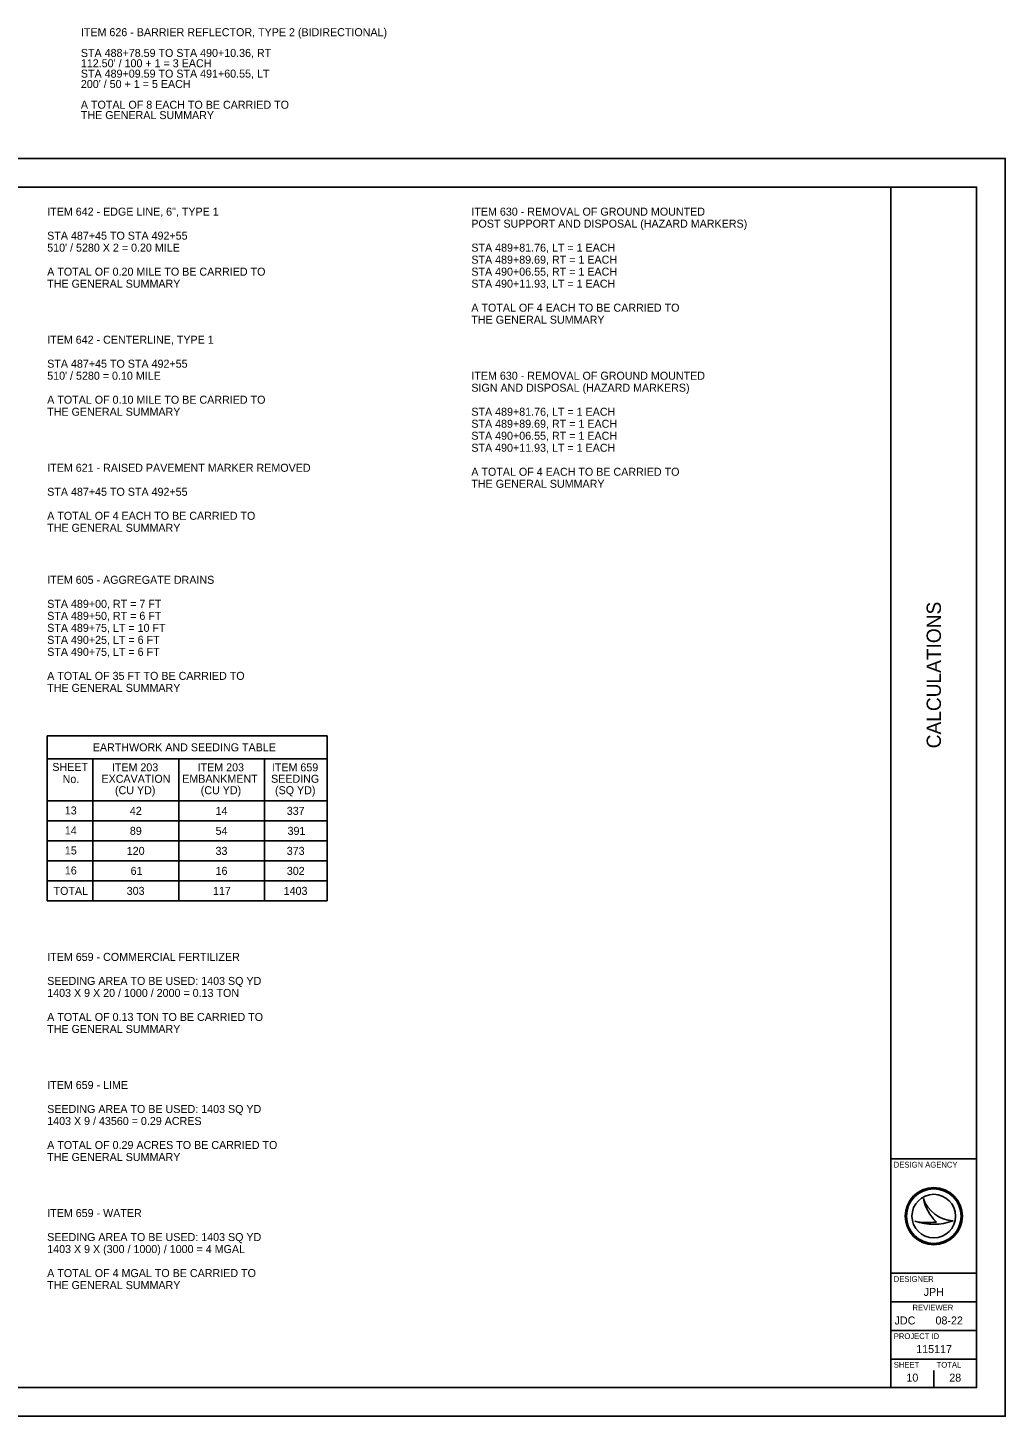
# Model space of a CAD drawing. Extents: x 0 to 34, y 0 to 24.3.
# Drawn here: x 16.9 to 34, y 0 to 24.29 of the extents above; entities that cross this region are included whole.
import ezdxf

# ---------------------------------------------------------------- set-up
doc = ezdxf.new("R2010")
doc.units = 0
for name, color, linetype in [('SH_Border', 7, 'Continuous'), ('SH_Cut_Line', 7, 'Continuous'), ('SH_Data', 7, 'Continuous'), ('TX_P_1', 7, 'Continuous')]:
    doc.layers.add(name, color=color, linetype=linetype)

msp = doc.modelspace()

# ---------------------------------------------------------------- linework, layer by layer
at = {"layer": 'SH_Border'}
for p, q in [((32, 0.5), (32, 21.5)), ((32, 4.5), (33.5, 4.5)), ((32, 2.5), (33.5, 2.5)), ((32, 2), (33.5, 2)), ((32, 1.5), (33.5, 1.5)), ((32, 1), (33.5, 1))]:
    msp.add_line(p, q, dxfattribs=at)
msp.add_lwpolyline([(1.5, 21.5), (33.5, 21.5), (33.5, 0.5), (1.5, 0.5)], close=True, dxfattribs=at)
at = {"layer": 'SH_Cut_Line'}
msp.add_lwpolyline([(0, 0), (34, 0), (34, 22), (0, 22)], close=True, dxfattribs=at)
at = {"layer": 'SH_Data'}
for p, q in [((32.567, 3.81), (32.567, 3.81)), ((32.417, 3.41), (32.417, 3.41)), ((32.75, 3.5), (32.75, 3.5)), ((33.087, 3.419), (33.087, 3.419)), ((32.75, 0.5), (32.75, 0.8)), ((32.375, 0.675), (32.375, 0.675))]:
    msp.add_line(p, q, dxfattribs=at)
for radius in [0.5, 0.477, 0.477, 0.382]:
    msp.add_circle((32.75, 3.5), radius, dxfattribs=at)
for centre, radius, start, end in [((33.116, 3.998), 0.58, 198.9257, 198.9319), ((33.347, 3.97), 0.796, 191.6379, 191.6421), ((33.116, 3.998), 0.58, 198.9319, 267.1657), ((33.347, 3.97), 0.796, 191.6421, 226.0947), ((32.739, 4.37), 1.013, 251.4576, 290.0832), ((32.648, 4.654), 1.266, 259.4964, 259.4995), ((32.739, 4.37), 1.013, 251.4527, 251.4576), ((32.648, 4.654), 1.266, 259.4995, 276.6672)]:
    msp.add_arc(centre, radius, start, end, dxfattribs=at)
at = {"layer": 'TX_P_1'}
for p, q in [((22.14, 11.9), (17.24, 11.9)), ((17.24, 11.9), (17.24, 9.014)), ((22.14, 11.9), (22.14, 9.014)), ((22.14, 11.5), (17.24, 11.5)), ((18.04, 11.5), (18.04, 9.014)), ((19.54, 11.5), (19.54, 9.014)), ((21.04, 11.5), (21.04, 9.014)), ((22.14, 10.764), (17.24, 10.764)), ((22.14, 10.414), (17.24, 10.414)), ((22.14, 10.064), (17.24, 10.064)), ((22.14, 9.714), (17.24, 9.714)), ((22.14, 9.364), (17.24, 9.364)), ((22.14, 9.364), (17.24, 9.364)), ((22.14, 9.014), (17.24, 9.014))]:
    msp.add_line(p, q, dxfattribs=at)

# ---------------------------------------------------------------- texts
at = {"layer": 'SH_Data'}
msp.add_text('CALCULATIONS', height=0.25, rotation=90, dxfattribs=at).set_placement((32.875, 11.683))
for s, height, p in [('DESIGN AGENCY', 0.1, (32.05, 4.35)), ('DESIGNER', 0.1, (32.05, 2.35)), ('JPH', 0.14, (32.573, 2.105)), ('REVIEWER', 0.1, (32.378, 1.85)), ('JDC', 0.14, (32.064, 1.605)), ('08-22', 0.14, (32.78, 1.605)), ('PROJECT ID', 0.1, (32.05, 1.35)), ('115117', 0.14, (32.443, 1.105)), ('SHEET', 0.1, (32.05, 0.85)), ('10', 0.14, (32.271, 0.605)), ('TOTAL', 0.1, (32.8, 0.85)), ('28', 0.14, (33.021, 0.605))]:
    msp.add_text(s, height=height, dxfattribs=at).set_placement(p)
at = {"layer": 'TX_P_1'}
for s, p in [('ITEM 626 - BARRIER REFLECTOR, TYPE 2 (BIDIRECTIONAL)', (17.829, 24.139)), ('STA 488+78.59 TO STA 490+10.36, RT', (17.829, 23.776)), ("112.50' / 100 + 1 = 3 EACH", (17.829, 23.595)), ('STA 489+09.59 TO STA 491+60.55, LT', (17.829, 23.414)), ("200' / 50 + 1 = 5 EACH", (17.829, 23.233)), ('A TOTAL OF 8 EACH TO BE CARRIED TO', (17.829, 22.87)), ('THE GENERAL SUMMARY', (17.829, 22.689)), ('ITEM 642 - EDGE LINE, 6", TYPE 1', (17.24, 21)), ('ITEM 630 - REMOVAL OF GROUND MOUNTED', (24.66, 21)), ('POST SUPPORT AND DISPOSAL (HAZARD MARKERS)', (24.66, 20.79)), ('STA 487+45 TO STA 492+55', (17.24, 20.58)), ("510' / 5280 X 2 = 0.20 MILE", (17.24, 20.37)), ('STA 489+81.76, LT = 1 EACH', (24.66, 20.37)), ('STA 489+89.69, RT = 1 EACH', (24.66, 20.16)), ('A TOTAL OF 0.20 MILE TO BE CARRIED TO', (17.24, 19.95)), ('STA 490+06.55, RT = 1 EACH', (24.66, 19.95)), ('THE GENERAL SUMMARY', (17.24, 19.74)), ('STA 490+11.93, LT = 1 EACH', (24.66, 19.74)), ('A TOTAL OF 4 EACH TO BE CARRIED TO', (24.66, 19.32)), ('THE GENERAL SUMMARY', (24.66, 19.11)), ('ITEM 642 - CENTERLINE, TYPE 1', (17.24, 18.76)), ('STA 487+45 TO STA 492+55', (17.24, 18.34)), ("510' / 5280 = 0.10 MILE", (17.24, 18.13)), ('ITEM 630 - REMOVAL OF GROUND MOUNTED', (24.66, 18.13)), ('SIGN AND DISPOSAL (HAZARD MARKERS)', (24.66, 17.92)), ('A TOTAL OF 0.10 MILE TO BE CARRIED TO', (17.24, 17.71)), ('THE GENERAL SUMMARY', (17.24, 17.5)), ('STA 489+81.76, LT = 1 EACH', (24.66, 17.5)), ('STA 489+89.69, RT = 1 EACH', (24.66, 17.29)), ('STA 490+06.55, RT = 1 EACH', (24.66, 17.08)), ('STA 490+11.93, LT = 1 EACH', (24.66, 16.87)), ('ITEM 621 - RAISED PAVEMENT MARKER REMOVED', (17.24, 16.52)), ('A TOTAL OF 4 EACH TO BE CARRIED TO', (24.66, 16.45)), ('THE GENERAL SUMMARY', (24.66, 16.24)), ('STA 487+45 TO STA 492+55', (17.24, 16.1)), ('A TOTAL OF 4 EACH TO BE CARRIED TO', (17.24, 15.68)), ('THE GENERAL SUMMARY', (17.24, 15.47)), ('ITEM 605 - AGGREGATE DRAINS', (17.24, 14.56)), ('STA 489+00, RT = 7 FT', (17.24, 14.14)), ('STA 489+50, RT = 6 FT', (17.24, 13.93)), ('STA 489+75, LT = 10 FT', (17.24, 13.72)), ('STA 490+25, LT = 6 FT', (17.24, 13.51)), ('STA 490+75, LT = 6 FT', (17.24, 13.3)), ('A TOTAL OF 35 FT TO BE CARRIED TO', (17.24, 12.88)), ('THE GENERAL SUMMARY', (17.24, 12.67)), ('EARTHWORK AND SEEDING TABLE', (18.037, 11.63)), ('SHEET', (17.33, 11.287)), ('ITEM 203', (18.371, 11.28)), ('ITEM 203', (19.871, 11.28)), ('ITEM 659', (21.17, 11.28)), ('No.', (17.51, 11.077)), ('EXCAVATION', (18.189, 11.08)), ('EMBANKMENT', (19.602, 11.08)), ('SEEDING', (21.156, 11.08)), ('(CU YD)', (18.426, 10.88)), ('(CU YD)', (19.926, 10.88)), ('(SQ YD)', (21.226, 10.88)), ('13', (17.548, 10.526)), ('42', (18.686, 10.519)), ('14', (20.186, 10.519)), ('337', (21.431, 10.519)), ('14', (17.549, 10.176)), ('89', (18.686, 10.169)), ('54', (20.186, 10.169)), ('391', (21.445, 10.169)), ('15', (17.549, 9.826)), ('120', (18.632, 9.819)), ('33', (20.185, 9.819)), ('373', (21.431, 9.819)), ('16', (17.549, 9.476)), ('61', (18.699, 9.469)), ('16', (20.186, 9.469)), ('302', (21.432, 9.469)), ('TOTAL', (17.351, 9.119)), ('303', (18.631, 9.119)), ('117', (20.139, 9.119)), ('1403', (21.377, 9.119)), ('ITEM 659 - COMMERCIAL FERTILIZER', (17.24, 7.964)), ('SEEDING AREA TO BE USED: 1403 SQ YD', (17.24, 7.544)), ('1403 X 9 X 20 / 1000 / 2000 = 0.13 TON', (17.24, 7.334)), ('A TOTAL OF 0.13 TON TO BE CARRIED TO', (17.24, 6.914)), ('THE GENERAL SUMMARY', (17.24, 6.704)), ('ITEM 659 - LIME', (17.24, 5.724)), ('SEEDING AREA TO BE USED: 1403 SQ YD', (17.24, 5.304)), ('1403 X 9 / 43560 = 0.29 ACRES', (17.24, 5.094)), ('A TOTAL OF 0.29 ACRES TO BE CARRIED TO', (17.24, 4.674)), ('THE GENERAL SUMMARY', (17.24, 4.464)), ('ITEM 659 - WATER', (17.24, 3.484)), ('SEEDING AREA TO BE USED: 1403 SQ YD', (17.24, 3.064)), ('1403 X 9 X (300 / 1000) / 1000 = 4 MGAL', (17.24, 2.854)), ('A TOTAL OF 4 MGAL TO BE CARRIED TO', (17.24, 2.434)), ('THE GENERAL SUMMARY', (17.24, 2.224))]:
    msp.add_text(s, height=0.14, dxfattribs=at).set_placement(p)

doc.saveas('drawing.dxf')
